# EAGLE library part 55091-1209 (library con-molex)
0.635 mm PITCH B TO B CONN. Source: http://www.molex.com/pdm_docs/sd/550911609_sd.pdf
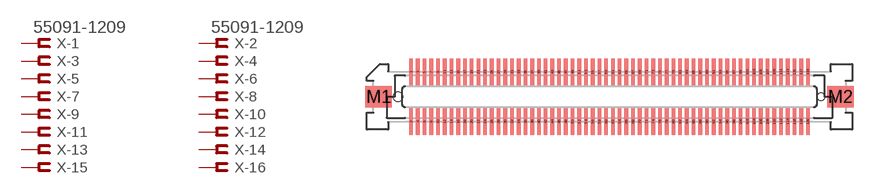
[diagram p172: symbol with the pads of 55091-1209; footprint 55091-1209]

Designator prefix X; gates -1=FV -2=FV -3=F -4=F -5=F -6=F -7=F -8=F -9=F -10=F -11=F -12=F -13=F -14=F -15=F -16=F -17=F -18=F -19=F -20=F -21=F -22=F -23=F -24=F -25=F -26=F -27=F -28=F -29=F -30=F -31=F -32=F -33=F -34=F -35=F -36=F -37=F -38=F -39=F -40=F -41=F -42=F -43=F -44=F -45=F -46=F -47=F -48=F -49=F -50=F -51=F -52=F -53=F -54=F -55=F -56=F -57=F -58=F -59=F -60=F -61=F -62=F -63=F -64=F -65=F -66=F -67=F -68=F -69=F -70=F -71=F -72=F -73=F -74=F -75=F -76=F -77=F -78=F -79=F -80=F -81=F -82=F -83=F -84=F -85=F -86=F -87=F -88=F -89=F -90=F -91=F -92=F -93=F -94=F -95=F -96=F -97=F -98=F -99=F -100=F -101=F -102=F -103=F -104=F -105=F -106=F -107=F -108=F -109=F -110=F -111=F -112=F -113=F -114=F -115=F -116=F -117=F -118=F -119=F -120=F

## 55091-1209 (OC_FARNELL: unknown; OC_NEWARK: unknown)  [55091-1209]
1  -1:S  pas
2  -2:S  pas
3  -3:S  pas
4  -4:S  pas
5  -5:S  pas
6  -6:S  pas
7  -7:S  pas
8  -8:S  pas
9  -9:S  pas
10  -10:S  pas
11  -11:S  pas
12  -12:S  pas
13  -13:S  pas
14  -14:S  pas
15  -15:S  pas
16  -16:S  pas
17  -17:S  pas
18  -18:S  pas
19  -19:S  pas
20  -20:S  pas
21  -21:S  pas
22  -22:S  pas
23  -23:S  pas
24  -24:S  pas
25  -25:S  pas
26  -26:S  pas
27  -27:S  pas
28  -28:S  pas
29  -29:S  pas
30  -30:S  pas
31  -31:S  pas
32  -32:S  pas
33  -33:S  pas
34  -34:S  pas
35  -35:S  pas
36  -36:S  pas
37  -37:S  pas
38  -38:S  pas
39  -39:S  pas
40  -40:S  pas
41  -41:S  pas
42  -42:S  pas
43  -43:S  pas
44  -44:S  pas
45  -45:S  pas
46  -46:S  pas
47  -47:S  pas
48  -48:S  pas
49  -49:S  pas
50  -50:S  pas
51  -51:S  pas
52  -52:S  pas
53  -53:S  pas
54  -54:S  pas
55  -55:S  pas
56  -56:S  pas
57  -57:S  pas
58  -58:S  pas
59  -59:S  pas
60  -60:S  pas
61  -61:S  pas
62  -62:S  pas
63  -63:S  pas
64  -64:S  pas
65  -65:S  pas
66  -66:S  pas
67  -67:S  pas
68  -68:S  pas
69  -69:S  pas
70  -70:S  pas
71  -71:S  pas
72  -72:S  pas
73  -73:S  pas
74  -74:S  pas
75  -75:S  pas
76  -76:S  pas
77  -77:S  pas
78  -78:S  pas
79  -79:S  pas
80  -80:S  pas
81  -81:S  pas
82  -82:S  pas
83  -83:S  pas
84  -84:S  pas
85  -85:S  pas
86  -86:S  pas
87  -87:S  pas
88  -88:S  pas
89  -89:S  pas
90  -90:S  pas
91  -91:S  pas
92  -92:S  pas
93  -93:S  pas
94  -94:S  pas
95  -95:S  pas
96  -96:S  pas
97  -97:S  pas
98  -98:S  pas
99  -99:S  pas
100  -100:S  pas
101  -101:S  pas
102  -102:S  pas
103  -103:S  pas
104  -104:S  pas
105  -105:S  pas
106  -106:S  pas
107  -107:S  pas
108  -108:S  pas
109  -109:S  pas
110  -110:S  pas
111  -111:S  pas
112  -112:S  pas
113  -113:S  pas
114  -114:S  pas
115  -115:S  pas
116  -116:S  pas
117  -117:S  pas
118  -118:S  pas
119  -119:S  pas
120  -120:S  pas

## Footprint 55091-1209 (pad centres in mm)
0.635 mm PITCH B TO B CONN. Source: http://www.molex.com/pdm_docs/sd/550911609_sd.pdf
smd 0.35 x 2.5: 1 -18.733,2.35; 2 -18.733,-2.35; 3 -18.098,2.35; 4 -18.098,-2.35; 5 -17.462,2.35; 6 -17.462,-2.35; 7 -16.828,2.35; 8 -16.828,-2.35; 9 -16.192,2.35; 10 -16.192,-2.35; 11 -15.557,2.35; 12 -15.557,-2.35; 13 -14.922,2.35; 14 -14.922,-2.35; 15 -14.287,2.35; 16 -14.287,-2.35; 17 -13.652,2.35; 18 -13.652,-2.35; 19 -13.018,2.35; 20 -13.018,-2.35; 21 -12.383,2.35; 22 -12.383,-2.35; 23 -11.748,2.35; 24 -11.748,-2.35; 25 -11.113,2.35; 26 -11.113,-2.35; 27 -10.477,2.35; 28 -10.477,-2.35; 29 -9.842,2.35; 30 -9.842,-2.35; 31 -9.207,2.35; 32 -9.207,-2.35; 33 -8.572,2.35; 34 -8.572,-2.35; 35 -7.938,2.35; 36 -7.938,-2.35; 37 -7.303,2.35; 38 -7.303,-2.35; 39 -6.668,2.35; 40 -6.668,-2.35; 41 -6.032,2.35; 42 -6.032,-2.35; 43 -5.397,2.35; 44 -5.397,-2.35; 45 -4.763,2.35; 46 -4.763,-2.35; 47 -4.128,2.35; 48 -4.128,-2.35; 49 -3.493,2.35; 50 -3.493,-2.35; 51 -2.857,2.35; 52 -2.857,-2.35; 53 -2.223,2.35; 54 -2.223,-2.35; 55 -1.587,2.35; 56 -1.587,-2.35; 57 -0.953,2.35; 58 -0.953,-2.35; 59 -0.318,2.35; 60 -0.318,-2.35; 61 0.318,2.35; 62 0.318,-2.35; 63 0.953,2.35; 64 0.953,-2.35; 65 1.587,2.35; 66 1.587,-2.35; 67 2.223,2.35; 68 2.223,-2.35; 69 2.857,2.35; 70 2.857,-2.35; 71 3.493,2.35; 72 3.493,-2.35; 73 4.128,2.35; 74 4.128,-2.35; 75 4.763,2.35; 76 4.763,-2.35; 77 5.397,2.35; 78 5.397,-2.35; 79 6.032,2.35; 80 6.032,-2.35; 81 6.668,2.35; 82 6.668,-2.35; 83 7.303,2.35; 84 7.303,-2.35; 85 7.938,2.35; 86 7.938,-2.35; 87 8.572,2.35; 88 8.572,-2.35; 89 9.207,2.35; 90 9.207,-2.35; 91 9.842,2.35; 92 9.842,-2.35; 93 10.477,2.35; 94 10.477,-2.35; 95 11.113,2.35; 96 11.113,-2.35; 97 11.748,2.35; 98 11.748,-2.35; 99 12.383,2.35; 100 12.383,-2.35; 101 13.018,2.35; 102 13.018,-2.35; 103 13.652,2.35; 104 13.652,-2.35; 105 14.287,2.35; 106 14.287,-2.35; 107 14.922,2.35; 108 14.922,-2.35; 109 15.557,2.35; 110 15.557,-2.35; 111 16.192,2.35; 112 16.192,-2.35; 113 16.828,2.35; 114 16.828,-2.35; 115 17.462,2.35; 116 17.462,-2.35; 117 18.098,2.35; 118 18.098,-2.35; 119 18.733,2.35; 120 18.733,-2.35
smd 2.5 x 2: M1 -21.8,0; M2 21.8,0
hole 0.9 at -19.985,0
hole 0.7 at 19.985,0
